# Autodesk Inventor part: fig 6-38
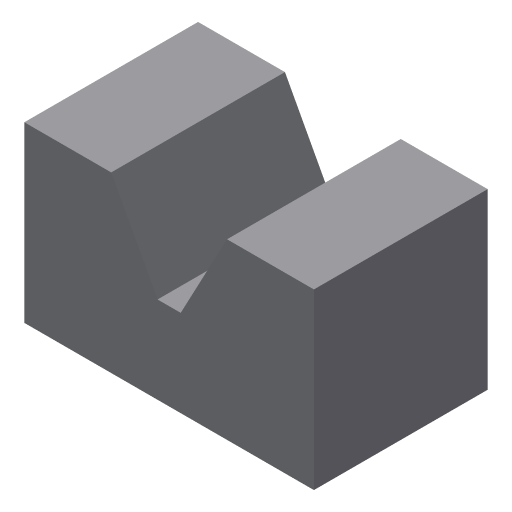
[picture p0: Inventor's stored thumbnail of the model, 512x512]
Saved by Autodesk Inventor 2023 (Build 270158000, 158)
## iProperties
Created: 2005-12
Part Number: fig 6-38
Document SubType Name: Modeling
Designer: CADCIM
Density: 1 g/cm^3
Material: Generic
Appearance: Default
Author: CADCIM
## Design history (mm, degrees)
sketch "Sketch1"
  geometry: L1 (10, 15)-(25, 15); L2 (25, 15)-(25, -15); L3 (25, -15)-(-25, -15); L4 (-25, -15)-(-25, 15); L5 (-25, 15)-(-10, 15); L6 (-10, 15)-(-2, 0); L7 (-2, 0)-(2, 0); L8 (2, 0)-(10, 15); 1 further point
  constraints: 16 end point, 3 equal length, 3 parallel, 1 collinear, 1 horizontal, 1 perpendicular, 1 other
  dimensions: "d0" = 50 distance of L2.end L3.end; "d1" = 25 distance from line of point (0, 0) L2; "d2" = 30 distance of L1.end L2.end; "d3" = 15 distance of L1.start L1.end; "d4" = 15 distance between parallel lines of L1 L7; "d5" = 4 distance of L6.end L7.end; "d6" = 15 distance from line of point (0, 0) L3
extrude "Extrusion1" new body sketch "Sketch1" stored distance "d7" = 30; taper "d8" = 0 deg
body "Solid1"
